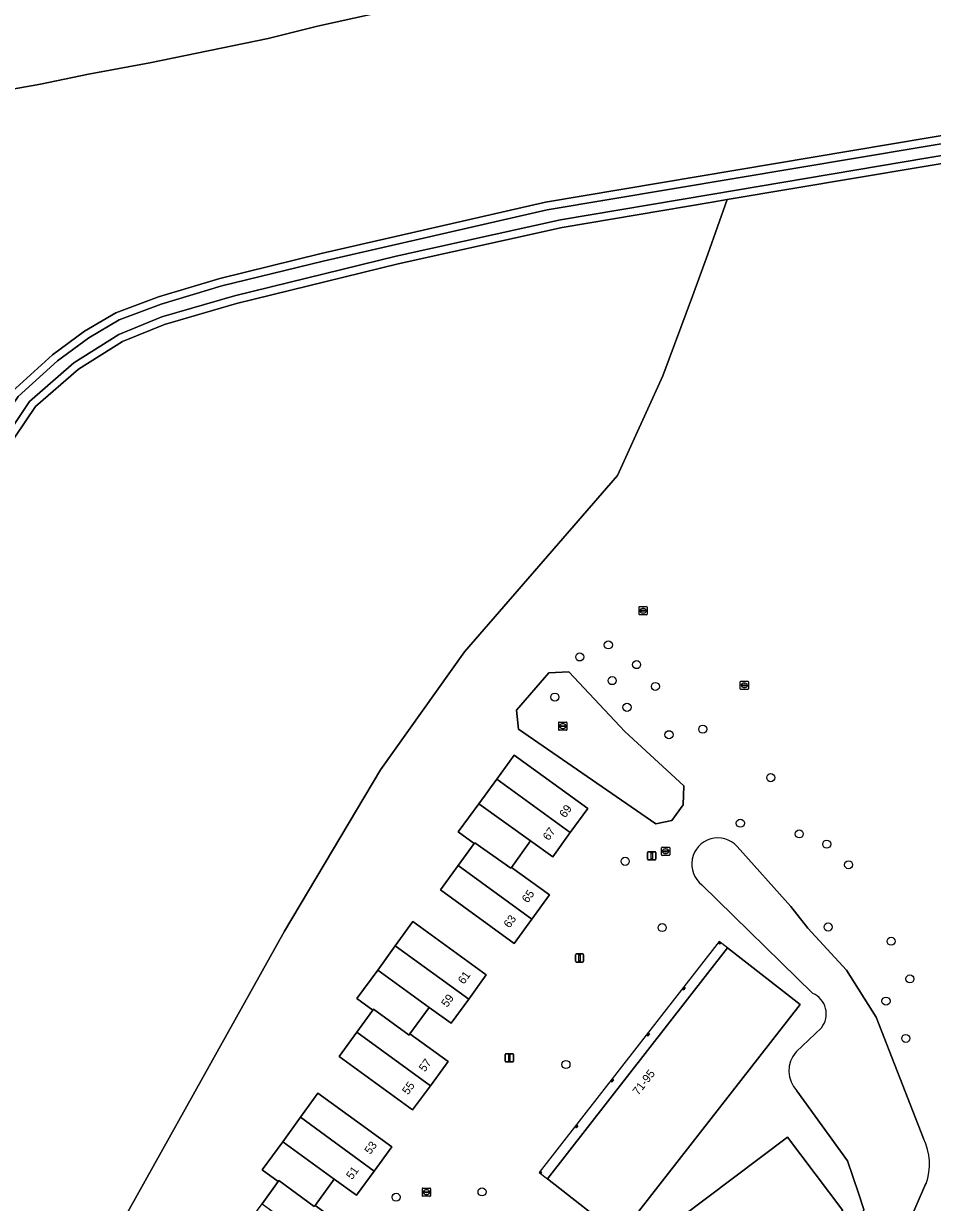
# Model space of a CAD drawing. Extents: x 159451 to 160664, y 388402 to 389723.
# Drawn here: x 159513.1 to 159623.4, y 389378.7 to 389521.7 of the extents above; entities that cross this region are included whole.
import ezdxf

# ---------------------------------------------------------------- set-up
doc = ezdxf.new("R2010")
doc.units = 0
for name, color, linetype in [('IMGEO_Boom', 7, 'Continuous'), ('IMGEO_Greppel_droge_sloot', 7, 'Continuous'), ('IMGEO_Groenvoorziening', 7, 'Continuous'), ('IMGEO_Lichtmast', 7, 'Continuous'), ('IMGEO_Loofbos', 7, 'Continuous'), ('IMGEO_Meer_plas_ven_vijver', 7, 'Continuous'), ('IMGEO_Oever', 7, 'Continuous'), ('IMGEO_Pand', 7, 'Continuous'), ('IMGEO_Pand_nummerreeks', 7, 'Continuous'), ('IMGEO_Pand_overbouw', 7, 'Continuous'), ('IMGEO_Rioolput', 7, 'Continuous')]:
    doc.layers.add(name, color=color, linetype=linetype)

msp = doc.modelspace()

# ---------------------------------------------------------------- linework, layer by layer
at = {"layer": 'IMGEO_Boom'}
for centre in [(159584.08, 389446.29), (159580.61, 389444.83), (159587.51, 389443.9), (159584.54, 389441.96), (159589.79, 389441.25), (159577.59, 389439.96), (159586.34, 389438.72), (159591.44, 389435.4), (159595.54, 389436.07), (159603.78, 389430.19), (159600.09, 389424.66), (159607.24, 389423.36), (159610.57, 389422.12), (159586.12, 389420.04), (159613.22, 389419.62), (159590.61, 389412), (159610.74, 389412.07), (159618.38, 389410.34), (159620.66, 389405.78), (159617.76, 389403.08), (159620.16, 389398.56), (159578.94, 389395.39), (159558.34, 389379.29), (159568.76, 389379.94)]:
    msp.add_circle(centre, 0.489, dxfattribs=at)
at = {"layer": 'IMGEO_Greppel_droge_sloot'}
for points in [[(159636.97, 389509.2), (159576.64, 389499.06), (159549.47, 389492.85), (159537.2, 389489.84), (159529.84, 389487.62), (159524.73, 389485.71), (159521.07, 389483.56), (159517.26, 389480.74), (159512.48, 389476.42), (159508.93, 389471.27), (159507.1, 389466.58), (159505.63, 389461.3), (159504.52, 389456.13), (159503.66, 389450.55), (159500.95, 389426.85), (159489.57, 389330.45)], [(159490.64, 389330.24), (159499.05, 389400.46), (159504.98, 389451.19), (159506.87, 389461.63), (159508.71, 389466.85), (159510.07, 389470.22), (159513.86, 389475.84), (159519.24, 389480.5), (159524.71, 389483.94), (159529.91, 389486.08), (159538.73, 389488.65), (159558.36, 389493.45), (159578.28, 389497.87), (159596.51, 389500.94), (159637.44, 389507.84)]]:
    msp.add_lwpolyline(points, dxfattribs=at)
at = {"layer": 'IMGEO_Groenvoorziening'}
for points in [[(159762.21, 389343.03), (159732.27, 389382.65), (159734.43, 389384.27), (159705.43, 389419.91), (159686.88, 389439.01), (159667.95, 389454.31), (159663.03, 389457.69), (159684.18, 389485.7), (159690.1, 389492.47), (159692.72, 389500), (159689.92, 389509.16), (159688.02, 389515.39), (159637.6, 389506.89), (159598.51, 389500.31), (159596.13, 389493.71), (159594.28, 389488.58), (159590.7, 389478.95), (159585.18, 389466.83), (159566.64, 389445.47), (159556.46, 389431.12), (159544.81, 389411.57), (159514.87, 389357.94)], [(159599.69, 389421.85), (159606.21, 389414.57), (159608.28, 389411.94), (159612.97, 389406.85), (159616.55, 389401.14), (159622.3, 389386.4)], [(159608.88, 389404.02), (159595.42, 389417.19)], [(159606.86, 389396.92), (159609.94, 389399.84)], [(159591.09, 389358.32), (159614.72, 389376.73), (159615.08, 389377.79), (159614.44, 389379.79), (159613.1, 389383.71), (159606.95, 389392.21)], [(159622.61, 389380.94), (159618.83, 389372.29)]]:
    msp.add_lwpolyline(points, dxfattribs=at)
for points in [[(159589.86, 389424.57), (159573.18, 389436.06), (159572.94, 389438.39), (159576.87, 389442.89), (159579.29, 389443.04), (159586.1, 389435.77), (159593.23, 389429.19), (159593.16, 389426.89), (159591.8, 389425)], [(159572.33, 389419.31), (159576.93, 389415.98), (159574.79, 389413.04), (159572.65, 389410.09), (159563.73, 389416.57), (159565.87, 389419.52), (159567.82, 389422.2), (159565.88, 389423.61), (159568.36, 389427.01), (159570.54, 389430.01), (159572.66, 389432.93), (159581.58, 389426.46), (159579.46, 389423.53), (159577.34, 389420.6), (159574.63, 389422.54)], [(159560.01, 389399.1), (159564.64, 389395.75), (159562.49, 389392.81), (159560.34, 389389.88), (159551.43, 389396.36), (159553.58, 389399.33), (159555.51, 389401.98), (159553.58, 389403.39), (159556.1, 389406.85), (159558.23, 389409.79), (159560.37, 389412.74), (159569.28, 389406.25), (159567.15, 389403.32), (159565.02, 389400.39), (159562.35, 389402.32)], [(159585.49, 389374.64), (159576.69, 389381.52), (159598.55, 389409.54), (159607.34, 389402.68)], [(159597.59, 389410.04), (159597.46, 389410.14), (159597.56, 389410.27), (159597.69, 389410.17)], [(159593.21, 389404.43), (159593.08, 389404.52), (159593.28, 389404.78), (159593.4, 389404.68)], [(159588.87, 389398.87), (159588.75, 389398.97), (159588.94, 389399.22), (159589.07, 389399.12)], [(159584.51, 389393.28), (159584.39, 389393.38), (159584.58, 389393.63), (159584.71, 389393.53)], [(159548.5, 389378.3), (159553.12, 389374.96), (159550.99, 389372.02), (159548.85, 389369.08), (159539.93, 389375.56), (159542.07, 389378.5), (159544.02, 389381.19), (159542.08, 389382.6), (159544.58, 389386.03), (159546.73, 389389), (159548.86, 389391.93), (159557.8, 389385.4), (159555.66, 389382.47), (159553.52, 389379.54), (159550.82, 389381.5)], [(159580.37, 389387.97), (159580.18, 389387.72), (159580.05, 389387.82), (159580.25, 389388.07)], [(159589.76, 389360.53), (159583.05, 389369.44), (159605.81, 389386.58), (159612.53, 389377.66)], [(159575.89, 389382.22), (159575.76, 389382.32), (159575.86, 389382.45), (159575.99, 389382.35)]]:
    msp.add_lwpolyline(points, close=True, dxfattribs=at)
for centre, radius, start, end in [((159597.36, 389419.7), 3.17, 42.4764, 232.4269), ((159607.78, 389401.52), 2.73, 322.1853, 66.2612), ((159609.5, 389394.61), 3.51, 138.9641, 223.3007), ((159616.21, 389383.31), 6.83, 339.6435, 26.8753)]:
    msp.add_arc(centre, radius, start, end, dxfattribs=at)
at = {"layer": 'IMGEO_Lichtmast'}
for p, q in [((159588.85, 389420.31), (159588.85, 389421.11)), ((159588.85, 389421.11), (159588.85, 389420.31)), ((159588.95, 389421.21), (159589.74, 389421.21)), ((159589.74, 389421.21), (159588.95, 389421.21)), ((159589.84, 389421.11), (159589.84, 389420.31)), ((159589.84, 389420.31), (159589.84, 389421.11)), ((159589.74, 389420.21), (159588.95, 389420.21)), ((159588.95, 389420.21), (159589.74, 389420.21)), ((159580.09, 389407.92), (159580.09, 389408.71)), ((159580.09, 389408.71), (159580.09, 389407.92)), ((159580.19, 389408.81), (159580.98, 389408.81)), ((159580.98, 389408.81), (159580.19, 389408.81)), ((159581.08, 389408.71), (159581.08, 389407.92)), ((159581.08, 389407.92), (159581.08, 389408.71)), ((159580.98, 389407.82), (159580.19, 389407.82)), ((159580.19, 389407.82), (159580.98, 389407.82)), ((159571.68, 389396.7), (159572.47, 389396.7)), ((159572.47, 389396.7), (159571.68, 389396.7)), ((159571.58, 389395.8), (159571.58, 389396.6)), ((159571.58, 389396.6), (159571.58, 389395.8)), ((159572.47, 389395.7), (159571.68, 389395.7)), ((159571.68, 389395.7), (159572.47, 389395.7)), ((159572.57, 389396.6), (159572.57, 389395.8)), ((159572.57, 389395.8), (159572.57, 389396.6))]:
    msp.add_line(p, q, dxfattribs=at)
for points in [[(159589.27, 389421.08), (159589.42, 389421.08), (159589.42, 389420.33), (159589.27, 389420.33), (159589.27, 389421.08)], [(159580.51, 389408.69), (159580.66, 389408.69), (159580.66, 389407.94), (159580.51, 389407.94), (159580.51, 389408.69)], [(159572, 389396.58), (159572.15, 389396.58), (159572.15, 389395.83), (159572, 389395.83), (159572, 389396.58)]]:
    msp.add_lwpolyline(points, dxfattribs=at)
for centre, start, end in [((159588.95, 389421.11), 90, 180), ((159588.95, 389421.11), 90, 180), ((159589.74, 389421.11), 0, 90), ((159589.74, 389421.11), 360, 90), ((159588.95, 389420.31), 180, 270), ((159588.95, 389420.31), 180, 270), ((159589.74, 389420.31), 270, 0), ((159589.74, 389420.31), 270, 0), ((159580.19, 389408.71), 90, 180), ((159580.19, 389408.71), 90, 180), ((159580.98, 389408.71), 0, 90), ((159580.98, 389408.71), 360, 90), ((159580.19, 389407.92), 180, 270), ((159580.19, 389407.92), 180, 270), ((159580.98, 389407.92), 270, 0), ((159580.98, 389407.92), 270, 0), ((159571.68, 389396.6), 90, 180), ((159571.68, 389396.6), 90, 180), ((159572.47, 389396.6), 0, 90), ((159572.47, 389396.6), 360, 90), ((159571.68, 389395.8), 180, 270), ((159571.68, 389395.8), 180, 270), ((159572.47, 389395.8), 270, 0), ((159572.47, 389395.8), 270, 0)]:
    msp.add_arc(centre, 0.1, start, end, dxfattribs=at)
at = {"layer": 'IMGEO_Loofbos'}
for points in [[(159461.4, 389523.29), (159463.65, 389518.08), (159466.19, 389517.21), (159467.54, 389516.53), (159469.54, 389515.51), (159474.39, 389514.86), (159478.26, 389513.99), (159481.7, 389512.58), (159486.3, 389511.71), (159491.43, 389510.98), (159495.02, 389511.51), (159499.7, 389511.56), (159505.2, 389512.43), (159510.41, 389513.47), (159515.21, 389514.3), (159521.04, 389515.55), (159528.48, 389516.92), (159542.8, 389519.87), (159548.8, 389521.36), (159555.24, 389522.78)], [(159555.24, 389522.78), (159548.8, 389521.36), (159542.8, 389519.87), (159528.48, 389516.92), (159521.04, 389515.55), (159515.21, 389514.3), (159510.41, 389513.47), (159505.2, 389512.43), (159499.7, 389511.56), (159495.02, 389511.51), (159491.43, 389510.98), (159486.3, 389511.71), (159481.7, 389512.58), (159478.26, 389513.99), (159474.39, 389514.86), (159469.54, 389515.51), (159467.54, 389516.53), (159475.08, 389318.79)], [(159488.62, 389330.56), (159500, 389426.96), (159502.71, 389450.67), (159503.58, 389456.3), (159504.7, 389461.53), (159506.19, 389466.88), (159508.08, 389471.72), (159511.76, 389477.05), (159516.65, 389481.48), (159520.54, 389484.36), (159524.32, 389486.57), (159529.53, 389488.52), (159536.95, 389490.76), (159549.25, 389493.78), (159576.46, 389500), (159636.81, 389510.14)], [(159544.81, 389411.57), (159556.46, 389431.12), (159566.64, 389445.47), (159585.18, 389466.83), (159590.7, 389478.95), (159594.28, 389488.58), (159596.13, 389493.71), (159598.51, 389500.31), (159596.67, 389500), (159578.46, 389496.93), (159558.58, 389492.52), (159538.98, 389487.72), (159530.23, 389485.17), (159525.15, 389483.08), (159519.81, 389479.73), (159514.58, 389475.2), (159510.92, 389469.77), (159509.61, 389466.52), (159507.8, 389461.38), (159505.93, 389451.05), (159500, 389400.35), (159491.59, 389330.09)], [(159475.09, 389317.38), (159476.8, 389293.94), (159485.81, 389295.21), (159491.99, 389308.12), (159504.18, 389336.44), (159514.87, 389357.94), (159544.81, 389411.57)]]:
    msp.add_lwpolyline(points, dxfattribs=at)
at = {"layer": 'IMGEO_Meer_plas_ven_vijver'}
msp.add_lwpolyline([(159589.86, 389424.57), (159591.8, 389425), (159593.16, 389426.89), (159593.23, 389429.19), (159586.1, 389435.77), (159579.29, 389443.04), (159576.87, 389442.89), (159572.94, 389438.39), (159573.18, 389436.06)], close=True, dxfattribs=at)
for points in [[(159622.3, 389386.4), (159616.55, 389401.14), (159612.97, 389406.85), (159608.28, 389411.94), (159606.21, 389414.57), (159599.69, 389421.85)], [(159595.42, 389417.19), (159608.88, 389404.02)], [(159609.94, 389399.84), (159606.86, 389396.92)], [(159606.95, 389392.21), (159613.1, 389383.71), (159614.44, 389379.79), (159615.08, 389377.79), (159614.72, 389376.73), (159591.09, 389358.32)], [(159618.83, 389372.29), (159622.61, 389380.94)]]:
    msp.add_lwpolyline(points, dxfattribs=at)
for centre, radius, start, end in [((159597.36, 389419.7), 3.17, 42.4764, 232.4269), ((159607.78, 389401.52), 2.73, 322.1853, 66.2612), ((159609.5, 389394.61), 3.51, 138.9641, 223.3007), ((159616.21, 389383.31), 6.83, 339.6435, 26.8753)]:
    msp.add_arc(centre, radius, start, end, dxfattribs=at)
at = {"layer": 'IMGEO_Oever'}
for points in [[(159636.81, 389510.14), (159576.46, 389500), (159549.25, 389493.78), (159536.95, 389490.76), (159529.53, 389488.52), (159524.32, 389486.57), (159520.54, 389484.36), (159516.65, 389481.48), (159511.76, 389477.05), (159508.08, 389471.72), (159506.19, 389466.88), (159504.7, 389461.53), (159503.58, 389456.3), (159502.71, 389450.67), (159500, 389426.96), (159488.62, 389330.56)], [(159489.57, 389330.45), (159500.95, 389426.85), (159503.66, 389450.55), (159504.52, 389456.13), (159505.63, 389461.3), (159507.1, 389466.58), (159508.93, 389471.27), (159512.48, 389476.42), (159517.26, 389480.74), (159521.07, 389483.56), (159524.73, 389485.71), (159529.84, 389487.62), (159537.2, 389489.84), (159549.47, 389492.85), (159576.64, 389499.06), (159636.97, 389509.2)], [(159637.44, 389507.84), (159596.51, 389500.94), (159578.28, 389497.87), (159558.36, 389493.45), (159538.73, 389488.65), (159529.91, 389486.08), (159524.71, 389483.94), (159519.24, 389480.5), (159513.86, 389475.84), (159510.07, 389470.22), (159508.71, 389466.85), (159506.87, 389461.63), (159504.98, 389451.19), (159499.05, 389400.46), (159490.64, 389330.24)], [(159491.59, 389330.09), (159500, 389400.35), (159505.93, 389451.05), (159507.8, 389461.38), (159509.61, 389466.52), (159510.92, 389469.77), (159514.58, 389475.2), (159519.81, 389479.73), (159525.15, 389483.08), (159530.23, 389485.17), (159538.98, 389487.72), (159558.58, 389492.52), (159578.46, 389496.93), (159596.67, 389500), (159598.51, 389500.31), (159637.6, 389506.89)]]:
    msp.add_lwpolyline(points, dxfattribs=at)
at = {"layer": 'IMGEO_Pand'}
for points in [[(159572.66, 389432.93), (159570.54, 389430.01), (159579.46, 389423.53), (159581.58, 389426.46)], [(159570.54, 389430.01), (159568.36, 389427.01), (159574.63, 389422.54), (159577.34, 389420.6), (159579.46, 389423.53)], [(159568.36, 389427.01), (159565.88, 389423.61), (159567.82, 389422.2), (159567.89, 389422.29), (159572.24, 389419.19), (159572.33, 389419.31), (159574.63, 389422.54)], [(159572.33, 389419.31), (159572.24, 389419.19), (159567.89, 389422.29), (159567.82, 389422.2), (159565.87, 389419.52), (159574.79, 389413.04), (159576.93, 389415.98)], [(159565.87, 389419.52), (159563.73, 389416.57), (159572.65, 389410.09), (159574.79, 389413.04)], [(159560.37, 389412.74), (159558.23, 389409.79), (159567.15, 389403.32), (159569.28, 389406.25)], [(159558.23, 389409.79), (159556.1, 389406.85), (159562.35, 389402.32), (159565.02, 389400.39), (159567.15, 389403.32)], [(159607.34, 389402.68), (159598.55, 389409.54), (159576.69, 389381.52), (159585.49, 389374.64)], [(159597.56, 389410.27), (159597.46, 389410.14), (159597.59, 389410.04), (159597.69, 389410.17)], [(159556.1, 389406.85), (159553.58, 389403.39), (159555.51, 389401.98), (159555.6, 389402.1), (159559.92, 389398.97), (159560.01, 389399.1), (159562.35, 389402.32)], [(159593.4, 389404.68), (159593.28, 389404.78), (159593.08, 389404.52), (159593.21, 389404.43)], [(159560.01, 389399.1), (159559.92, 389398.97), (159555.6, 389402.1), (159555.51, 389401.98), (159553.58, 389399.33), (159562.49, 389392.81), (159564.64, 389395.75)], [(159553.58, 389399.33), (159551.43, 389396.36), (159560.34, 389389.88), (159562.49, 389392.81)], [(159589.07, 389399.12), (159588.94, 389399.22), (159588.75, 389398.97), (159588.87, 389398.87)], [(159584.71, 389393.53), (159584.58, 389393.63), (159584.39, 389393.38), (159584.51, 389393.28)], [(159548.86, 389391.93), (159546.73, 389389), (159555.66, 389382.47), (159557.8, 389385.4)], [(159546.73, 389389), (159544.58, 389386.03), (159550.82, 389381.5), (159553.52, 389379.54), (159555.66, 389382.47)], [(159580.37, 389387.97), (159580.25, 389388.07), (159580.05, 389387.82), (159580.18, 389387.72)], [(159544.58, 389386.03), (159542.08, 389382.6), (159544.02, 389381.19), (159544.11, 389381.3), (159548.41, 389378.18), (159548.5, 389378.3), (159550.82, 389381.5)], [(159612.53, 389377.66), (159605.81, 389386.58), (159583.05, 389369.44), (159589.76, 389360.53)], [(159575.89, 389382.22), (159575.99, 389382.35), (159575.86, 389382.45), (159575.76, 389382.32)], [(159548.5, 389378.3), (159548.41, 389378.18), (159544.11, 389381.3), (159544.02, 389381.19), (159542.07, 389378.5), (159550.99, 389372.02), (159553.12, 389374.96)]]:
    msp.add_lwpolyline(points, close=True, dxfattribs=at)
at = {"layer": 'IMGEO_Pand_overbouw'}
msp.add_lwpolyline([(159598.55, 389409.54), (159597.53, 389410.33), (159575.67, 389382.31), (159576.69, 389381.52)], close=True, dxfattribs=at)
at = {"layer": 'IMGEO_Rioolput'}
for p, q in [((159587.8, 389450.02), (159587.8, 389450.87)), ((159587.87, 389450.94), (159588.72, 389450.94)), ((159588.72, 389449.94), (159587.87, 389449.94)), ((159588.05, 389450.44), (159588.05, 389450.45)), ((159588.49, 389450.4), (159588.09, 389450.4)), ((159588.1, 389450.49), (159588.5, 389450.49)), ((159588.28, 389450.72), (159588.31, 389450.72)), ((159588.31, 389450.16), (159588.28, 389450.16)), ((159588.54, 389450.45), (159588.54, 389450.44)), ((159588.8, 389450.87), (159588.8, 389450.02)), ((159600.08, 389440.96), (159600.08, 389441.81)), ((159600.15, 389441.89), (159601.01, 389441.89)), ((159600.34, 389441.38), (159600.34, 389441.39)), ((159600.38, 389441.43), (159600.78, 389441.43)), ((159600.78, 389441.34), (159600.38, 389441.34)), ((159600.59, 389441.11), (159600.56, 389441.11)), ((159600.57, 389441.67), (159600.59, 389441.67)), ((159600.82, 389441.39), (159600.82, 389441.38)), ((159601.08, 389441.81), (159601.08, 389440.96)), ((159601.01, 389440.89), (159600.15, 389440.89)), ((159578.06, 389436.01), (159578.06, 389436.86)), ((159578.13, 389436.94), (159578.98, 389436.94)), ((159578.54, 389436.72), (159578.57, 389436.72)), ((159579.06, 389436.86), (159579.06, 389436.01)), ((159578.98, 389435.94), (159578.13, 389435.94)), ((159578.31, 389436.43), (159578.31, 389436.44)), ((159578.75, 389436.39), (159578.35, 389436.39)), ((159578.36, 389436.48), (159578.76, 389436.48)), ((159578.57, 389436.16), (159578.54, 389436.16)), ((159578.8, 389436.44), (159578.8, 389436.43)), ((159590.53, 389420.83), (159590.53, 389421.68)), ((159590.6, 389421.76), (159591.45, 389421.76)), ((159590.79, 389421.25), (159590.79, 389421.26)), ((159590.83, 389421.3), (159591.23, 389421.3)), ((159591.22, 389421.21), (159590.83, 389421.21)), ((159591.04, 389420.98), (159591.01, 389420.98)), ((159591.02, 389421.54), (159591.04, 389421.54)), ((159591.27, 389421.26), (159591.27, 389421.25)), ((159591.53, 389421.68), (159591.53, 389420.83)), ((159591.45, 389420.76), (159590.6, 389420.76)), ((159561.52, 389379.47), (159561.52, 389380.32)), ((159561.59, 389380.4), (159562.44, 389380.4)), ((159561.78, 389379.89), (159561.78, 389379.9)), ((159561.82, 389379.94), (159562.22, 389379.94)), ((159562.21, 389379.85), (159561.82, 389379.85)), ((159562.03, 389379.62), (159562, 389379.62)), ((159562.01, 389380.18), (159562.03, 389380.18)), ((159562.26, 389379.9), (159562.26, 389379.89)), ((159562.52, 389380.32), (159562.52, 389379.47)), ((159562.44, 389379.4), (159561.59, 389379.4))]:
    msp.add_line(p, q, dxfattribs=at)
for points in [[(159587.8, 389450.02), (159587.8, 389450.87)], [(159587.87, 389450.94), (159588.72, 389450.94)], [(159588.72, 389449.94), (159587.87, 389449.94)], [(159588.8, 389450.87), (159588.8, 389450.02)], [(159600.08, 389440.96), (159600.08, 389441.81)], [(159600.15, 389441.89), (159601.01, 389441.89)], [(159601.08, 389441.81), (159601.08, 389440.96)], [(159601.01, 389440.89), (159600.15, 389440.89)], [(159578.06, 389436.01), (159578.06, 389436.86)], [(159578.13, 389436.94), (159578.98, 389436.94)], [(159579.06, 389436.86), (159579.06, 389436.01)], [(159578.98, 389435.94), (159578.13, 389435.94)], [(159590.53, 389420.83), (159590.53, 389421.68)], [(159590.6, 389421.76), (159591.45, 389421.76)], [(159591.53, 389421.68), (159591.53, 389420.83)], [(159591.45, 389420.76), (159590.6, 389420.76)], [(159561.52, 389379.47), (159561.52, 389380.32)], [(159561.59, 389380.4), (159562.44, 389380.4)], [(159562.52, 389380.32), (159562.52, 389379.47)], [(159562.44, 389379.4), (159561.59, 389379.4)]]:
    msp.add_lwpolyline(points, dxfattribs=at)
for centre, radius, start, end in [((159587.87, 389450.87), 0.0765, 91.552, 178.448), ((159587.87, 389450.87), 0.0765, 91.552, 178.448), ((159587.87, 389450.02), 0.0765, 181.552, 268.448), ((159587.87, 389450.02), 0.0765, 181.552, 268.448), ((159588.1, 389450.45), 0.0403, 85.8775, 175.7526), ((159588.09, 389450.44), 0.0366, 178.938, 274.7102), ((159588.5, 389450.44), 0.043, 264.8664, 352.4533), ((159588.5, 389450.45), 0.0386, 1.7309, 96.639), ((159588.72, 389450.87), 0.0765, 1.552, 88.448), ((159588.72, 389450.87), 0.0765, 1.552, 88.448), ((159588.72, 389450.02), 0.0765, 271.552, 358.448), ((159588.72, 389450.02), 0.0765, 271.552, 358.448), ((159600.16, 389441.81), 0.0765, 91.552, 178.448), ((159600.16, 389441.81), 0.0765, 91.552, 178.448), ((159600.16, 389440.96), 0.0765, 181.552, 268.448), ((159600.16, 389440.96), 0.0765, 181.552, 268.448), ((159600.38, 389441.39), 0.0403, 85.8775, 175.7526), ((159600.37, 389441.38), 0.0366, 178.938, 274.7102), ((159600.78, 389441.39), 0.0386, 1.7309, 96.639), ((159600.78, 389441.39), 0.043, 264.8664, 352.4533), ((159601, 389441.81), 0.0765, 1.552, 88.448), ((159601, 389441.81), 0.0765, 1.552, 88.448), ((159601, 389440.96), 0.0765, 271.552, 358.448), ((159601, 389440.96), 0.0765, 271.552, 358.448), ((159578.13, 389436.86), 0.0765, 91.552, 178.448), ((159578.13, 389436.86), 0.0765, 91.552, 178.448), ((159578.98, 389436.86), 0.0765, 1.552, 88.448), ((159578.98, 389436.86), 0.0765, 1.552, 88.448), ((159578.13, 389436.01), 0.0765, 181.552, 268.448), ((159578.13, 389436.01), 0.0765, 181.552, 268.448), ((159578.36, 389436.44), 0.0403, 85.8775, 175.7526), ((159578.35, 389436.43), 0.0366, 178.938, 274.7102), ((159578.76, 389436.44), 0.043, 264.8664, 352.4533), ((159578.76, 389436.44), 0.0386, 1.7309, 96.639), ((159578.98, 389436.01), 0.0765, 271.552, 358.448), ((159578.98, 389436.01), 0.0765, 271.552, 358.448), ((159590.6, 389421.68), 0.0765, 91.552, 178.448), ((159590.6, 389421.68), 0.0765, 91.552, 178.448), ((159590.83, 389421.26), 0.0403, 85.8775, 175.7526), ((159590.82, 389421.25), 0.0366, 178.938, 274.7102), ((159591.23, 389421.26), 0.043, 264.8664, 352.4533), ((159591.23, 389421.26), 0.0386, 1.7309, 96.639), ((159591.45, 389421.68), 0.0765, 1.552, 88.448), ((159591.45, 389421.68), 0.0765, 1.552, 88.448), ((159590.6, 389420.83), 0.0765, 181.552, 268.448), ((159590.6, 389420.83), 0.0765, 181.552, 268.448), ((159591.45, 389420.83), 0.0765, 271.552, 358.448), ((159591.45, 389420.83), 0.0765, 271.552, 358.448), ((159561.59, 389380.32), 0.0765, 91.552, 178.448), ((159561.59, 389380.32), 0.0765, 91.552, 178.448), ((159561.59, 389379.47), 0.0765, 181.552, 268.448), ((159561.59, 389379.47), 0.0765, 181.552, 268.448), ((159561.82, 389379.9), 0.0403, 85.8775, 175.7526), ((159561.81, 389379.89), 0.0366, 178.938, 274.7102), ((159562.22, 389379.9), 0.043, 264.8664, 352.4533), ((159562.22, 389379.9), 0.0386, 1.7309, 96.639), ((159562.44, 389380.32), 0.0765, 1.552, 88.448), ((159562.44, 389380.32), 0.0765, 1.552, 88.448), ((159562.44, 389379.47), 0.0765, 271.552, 358.448), ((159562.44, 389379.47), 0.0765, 271.552, 358.448)]:
    msp.add_arc(centre, radius, start, end, dxfattribs=at)
for centre, major_axis, ratio, start_param, end_param in [((159588.28, 389450.44), (-0.387, 0.002), 0.722429, 4.712389, 7.853982), ((159588.31, 389450.44), (-0.39, 0.002), 0.717154, 1.570796, 4.712389), ((159600.57, 389441.39), (-0.387, 0.002), 0.722429, 4.712389, 7.853982), ((159600.59, 389441.39), (-0.39, 0.002), 0.717154, 1.570796, 4.712389), ((159578.54, 389436.44), (-0.387, 0.002), 0.722429, 4.712389, 7.853982), ((159578.57, 389436.44), (-0.39, 0.002), 0.717154, 1.570796, 4.712389), ((159591.01, 389421.26), (-0.387, 0.002), 0.722429, 4.712389, 7.853982), ((159591.04, 389421.26), (-0.39, 0.002), 0.717154, 1.570796, 4.712389), ((159562, 389379.9), (-0.387, 0.002), 0.722429, 4.712389, 7.853982), ((159562.03, 389379.9), (-0.39, 0.002), 0.717154, 1.570796, 4.712389)]:
    msp.add_ellipse(centre, major_axis=major_axis, ratio=ratio, start_param=start_param, end_param=end_param, dxfattribs=at)

# ---------------------------------------------------------------- texts
at = {"layer": 'IMGEO_Pand_nummerreeks'}
for s, rotation, p in [('69', 54.0242, (159578.85, 389425.24)), ('67', 54.0242, (159576.85, 389422.48)), ('65', 53.9784, (159574.3, 389414.91)), ('63', 53.9784, (159572.09, 389411.87)), ('61', 54.0528, (159566.55, 389405.05)), ('59', 54.0528, (159564.53, 389402.26)), ('57', 53.8007, (159561.81, 389394.42)), ('71-95', 52.0418, (159587.71, 389391.58)), ('55', 53.8007, (159559.78, 389391.64)), ('53', 53.8122, (159555.21, 389384.41)), ('51', 53.8122, (159552.99, 389381.36))]:
    msp.add_text(s, height=1, rotation=rotation, dxfattribs=at).set_placement(p)

doc.saveas('drawing.dxf')
